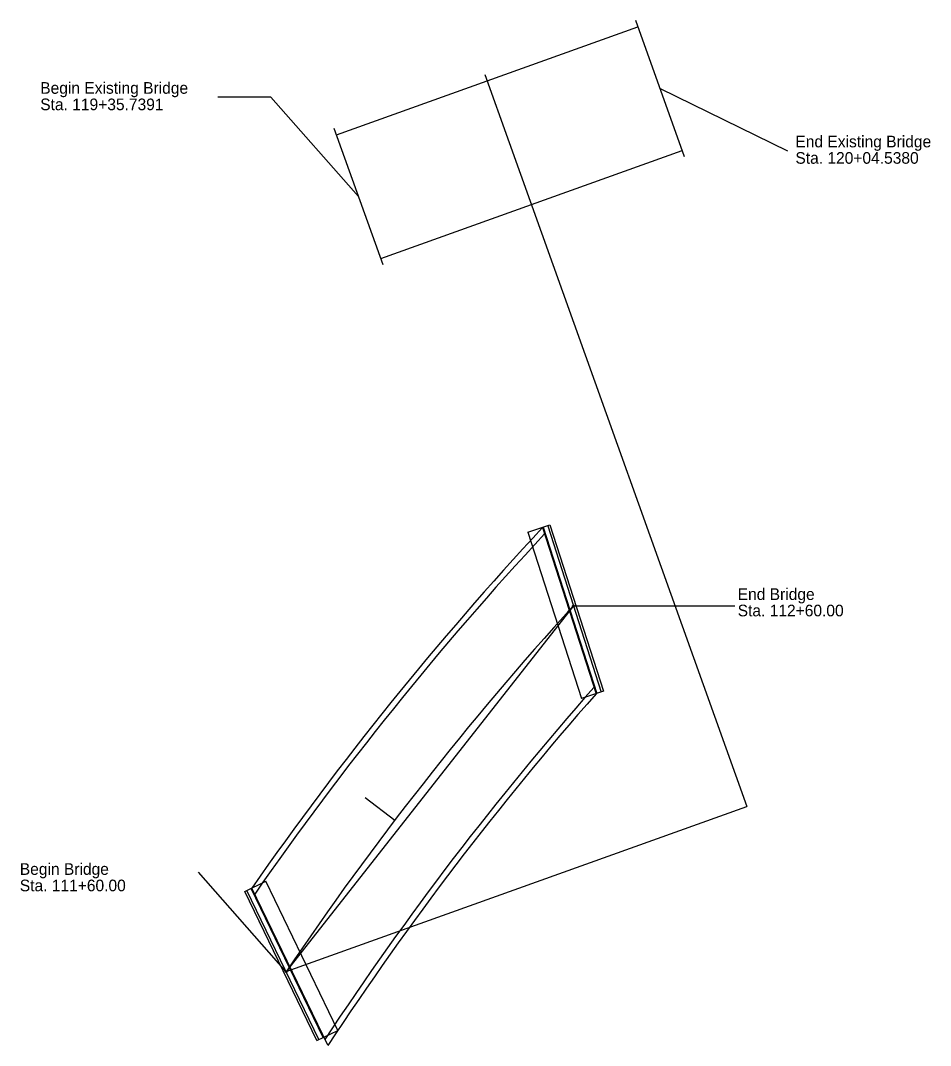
# Model space of a CAD drawing. Extents: x 170 to 365, y -124 to 97.
import ezdxf

# ---------------------------------------------------------------- set-up
doc = ezdxf.new("R2010")
doc.units = 0
doc.layers.add('ALI_DESIGN_ML_TICS', color=7, linetype='Continuous')
doc.layers.add('Level 1', color=7, linetype='Continuous')

msp = doc.modelspace()

# ---------------------------------------------------------------- linework, layer by layer
at = {"layer": 'ALI_DESIGN_ML_TICS'}
msp.add_line((250.04, -75.22), (243.68, -70.37), dxfattribs=at)
at = {"layer": 'Level 1'}
for p, q in [((237.51, 72.03), (302.28, 95.22)), ((312.28, 67.31), (301.8, 96.59)), ((269.41, 84.99), (274.65, 70.35)), ((307.04, 81.95), (334.39, 68.62)), ((223.43, 80.15), (212.02, 80.15)), ((242.27, 58.75), (223.43, 80.15)), ((247.51, 44.12), (237.02, 73.39)), ((247.02, 45.48), (311.79, 68.68)), ((274.65, 70.35), (325.71, -72.25)), ((278.61, -13.31), (283.37, -11.77)), ((281.79, -12.28), (293.3, -48)), ((281.87, -12.26), (293.38, -47.97)), ((281.95, -12.23), (293.46, -47.95)), ((282.9, -11.92), (294.41, -47.64)), ((283.37, -11.77), (294.89, -47.49)), ((278.61, -13.31), (290.13, -49.02)), ((288.45, -29.15), (226.7, -107.7)), ((288.45, -29.15), (323.11, -29.15)), ((294.89, -47.49), (290.13, -49.02)), ((226.7, -107.7), (325.71, -72.25)), ((226.7, -107.71), (207.87, -86.31)), ((217.82, -90.46), (222.32, -88.29)), ((233.75, -122.29), (218.27, -90.25)), ((234.65, -121.85), (219.17, -89.81)), ((234.73, -121.82), (219.24, -89.77)), ((235.64, -123.51), (219.32, -89.74)), ((237.8, -120.33), (222.32, -88.29)), ((233.3, -122.5), (217.82, -90.46)), ((233.3, -122.5), (237.8, -120.33))]:
    msp.add_line(p, q, dxfattribs=at)
for centre in [(288.45, -29.15), (226.7, -107.7)]:
    msp.add_circle(centre, 0.192, dxfattribs=at)
for centre, radius, start, end in [((802.43, -496.11), 710.74, 137.09923, 145.12754), ((802.43, -496.11), 709.49, 137.15572, 145.18429), ((802.43, -496.11), 694.49, 137.74844, 145.99845), ((802.45, -496.07), 694.49, 137.74844, 137.91296), ((802.43, -496.11), 679.49, 138.58454, 146.61955), ((802.43, -496.11), 678.24, 138.64729, 146.68259), ((802.45, -496.07), 694.49, 145.83345, 145.99845)]:
    msp.add_arc(centre, radius, start, end, dxfattribs=at)

# ---------------------------------------------------------------- texts
for s, p in [('Begin Existing Bridge ', (173.86, 80.85)), ('Sta. 119+35.7391', (173.86, 77.32)), ('End Existing Bridge ', (336.12, 69.34)), ('Sta. 120+04.5380', (336.12, 65.82)), ('End Bridge ', (323.72, -27.87)), ('Sta. 112+60.00', (323.72, -31.39)), ('Begin Bridge ', (169.47, -86.91)), ('Sta. 111+60.00', (169.47, -90.44))]:
    msp.add_text(s, height=2.5, dxfattribs=at).set_placement(p)

doc.saveas('drawing.dxf')
